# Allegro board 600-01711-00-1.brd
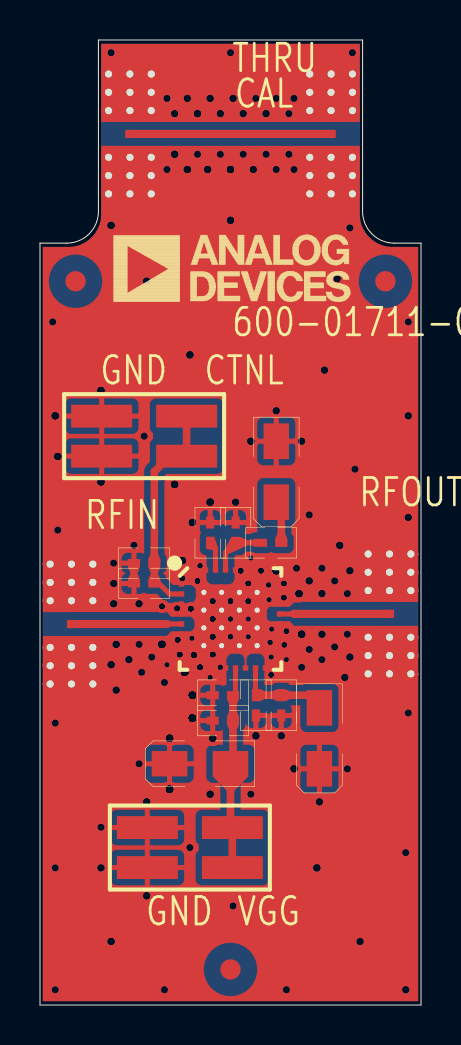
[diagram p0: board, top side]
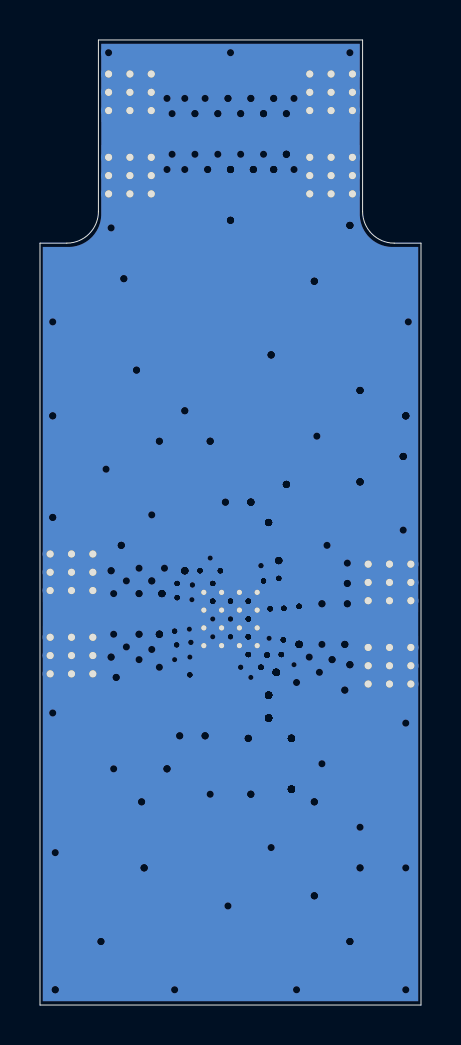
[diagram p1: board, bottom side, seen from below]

Outline 19.05 x 48.26 mm; copper layers: TOP, BOTTOM. Coordinates in mm from the lower left corner of the outline.
Outline path: 0,38.1 1.33,38.1 arc(2.46,38.56) 2.92,39.69 2.92,48.26 16.13,48.26 16.13,39.69 arc(16.59,38.56) 17.72,38.1 19.05,38.1 19.05,0 0,0 0,38.1

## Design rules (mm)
net group RF_E: nets RFIN RFOUT THRU-CAL

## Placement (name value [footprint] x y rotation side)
1  -  [FID]  9.53 1.78 0 top
2  -  [FID]  1.78 36.2 0 top
3  -  [FID]  17.27 36.2 0 top
C1  .10  [0402]  8.51 23.62 270 top
C2  .10  [0402]  5.21 21.08 180 top
C3  .10  [0402]  9.14 15.49 180 top
C4  .10  [0402]  10.79 14.99 270 top
C5  .10  [0402]  9.78 23.62 90 top
C6  .10  [0402]  5.21 22.1 180 top
C7  .10  [0402]  9.14 14.22 180 top
C8  .10  [0402]  12.06 14.99 270 top
C9  .10  [3216]  11.81 26.67 270 top
C10  .10  [3216]  13.97 13.34 270 top
C11  .10  [3216]  8 12.06 180 top
J1  -  [K_SRI-NS]  0 19.05 0 top
J2  -  [K_SRI-NS]  19.05 19.56 180 top
J3  -  [HEADER_2MM_SMT_04PIN]  5.21 28.45 90 top
J4  -  [HEADER_2MM_SMT_04PIN]  7.49 7.87 90 top
J5  -  [K_SRI-NS]  16.13 43.56 180 top
J6  -  [K_SRI-NS]  2.92 43.56 0 top
R1  .10  [0402]  11.56 23.11 0 top
U1  -  [HMC_PM5]  9.53 19.3 0 top

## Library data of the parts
1-3 = FID-UNREGISTERED
C1-C8 = CAP: alternate symbols: (01005,0201,0302BB,0402,0402-EP,0502BB,0603,0805,1206,1210,1812,1825,2220,800A,CASEL,CASES)
C9-C11 = CAP_POL: alternate symbols: (0805POL,134D-F,2214,2915,2917,3216,3528,6032,7343,CAPFM-12_5,FK-P)
J1 J2 J5 J6 = K_SRI-NS: alternate symbols: (K_SRI-44GHZ,K_SRI-NS)
J3 J4 = 87759-0414
R1 = RES: alternate symbols: (0201,0302-EP,0402,0402-EP,0505-EP,0603,0603-EP,0805,1206,1206-EP,1210,2010-EP,2512)
U1 = HMC994APM5E

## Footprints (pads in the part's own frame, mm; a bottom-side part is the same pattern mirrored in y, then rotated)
0402
  rect 0.61x0.406 smd: 1(-0.508,0) 2(0.508,0)
3216
  rect 1.778x1.27 smd: 1(1.524,0) 2(-1.524,0)
FID
  round 1.016 smd: 1(0,0)
HEADER_2MM_SMT_04PIN
  rect 1.143x3.048 smd: 1(-1,-2.125) 2(-1,2.125) 3(1,-2.125) 4(1,2.125)
HMC_PM5
  rect 0.27x0.27 smd: 1(-2.45,1.75) 2(-2.45,1.25) 3(-2.45,0.75) 4(-2.45,0.25) 5(-2.45,-0.25) 6(-2.45,-0.75) 7(-2.45,-1.25) 8(-2.45,-1.75) 9(-1.75,-2.45) 10(-1.25,-2.45) 11(-0.75,-2.45) 12(-0.25,-2.45) 13(0.25,-2.45) 14(0.75,-2.45) 15(1.25,-2.45) 16(1.75,-2.45) 17(2.45,-1.75) 18(2.45,-1.25) 19(2.45,-0.75) 20(2.45,-0.25) 21(2.45,0.25) 22(2.45,0.75) 23(2.45,1.25) 24(2.45,1.75) 25(1.75,2.45) 26(1.25,2.45) 27(0.75,2.45) 28(0.25,2.45) 29(-0.25,2.45) 30(-0.75,2.45) 31(-1.25,2.45) 32(-1.75,2.45)
  round 0.635 hole 0.254: 33(-1.333,1.333) 34(-0.445,1.333) 35(0.445,1.333) 36(1.333,1.333) 37(-1.333,0.445) 38(-0.445,0.445) 39(0.445,0.445) 40(1.333,0.445) 41(-1.333,-0.445) 42(-0.445,-0.445) 43(0.445,-0.445) 44(1.333,-0.445) 45(-1.333,-1.333) 46(-0.445,-1.333) 47(0.445,-1.333) 48(1.333,-1.333)
K_SRI-NS
  rect 0.406x0.406 smd: 1(1.549,0)
  round 0.762 hole 0.356: 2(0.508,-2.997) 3(0.508,-2.083) 4(0.508,-1.168) 5(0.508,1.168) 6(0.508,2.083) 7(0.508,2.997) 8(1.575,-2.997) 9(1.575,-2.083) 10(1.575,-1.168) 11(1.575,1.168) 12(1.575,2.083) 13(1.575,2.997) 14(2.642,-2.997) 15(2.642,-2.083) 16(2.642,-1.168) 17(2.642,1.168) 18(2.642,2.083) 19(2.642,2.997)

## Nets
GND: C1.1 C2.2 C3.2 C4.2 C5.2 C6.2 C7.2 C8.2 C9.2 C10.1 C11.1 J1.2 J1.3 J1.4 J1.5 J1.6 J1.7 J1.8 J1.9 J1.10 J1.11 J1.12 J1.13 J1.14 J1.15 J1.16 J1.17 J1.18 J1.19 J2.2 J2.3 J2.4 J2.5 J2.6 J2.7 J2.8 J2.9 J2.10 J2.11 J2.12 J2.13 J2.14 J2.15 J2.16 J2.17 J2.18 J2.19 J3.2 J3.4 J4.2 J4.4 J5.2 J5.3 J5.4 J5.5 J5.6 J5.7 J5.8 J5.9 J5.10 J5.11 J5.12 J5.13 J5.14 J5.15 J5.16 J5.17 J5.18 J5.19 J6.2 J6.3 J6.4 J6.5 J6.6 J6.7 J6.8 J6.9 J6.10 J6.11 J6.12 J6.13 J6.14 J6.15 J6.16 J6.17 J6.18 J6.19 U1.1 U1.3 U1.4 U1.6 U1.7 U1.8 U1.9 U1.10 U1.11 U1.12 U1.14 U1.16 U1.17 U1.18 U1.19 U1.20 U1.22 U1.23 U1.24 U1.25 U1.26 U1.27 U1.28 U1.31 U1.32 U1.33 U1.34 U1.35 U1.36 U1.37 U1.38 U1.39 U1.40 U1.41 U1.42 U1.43 U1.44 U1.45 U1.46 U1.47 U1.48
CNTL: C2.1 C6.1 J3.1 J3.3 U1.2
RFIN: J1.1 U1.5
RFOUT: J2.1 U1.21
THRU-CAL: J5.1 J6.1
VGG: C3.1 C7.1 C11.2 J4.1 J4.3 U1.13
$1N162: C4.1 C8.1 C10.2 U1.15
$1N213: C5.1 R1.1 U1.29
$1N283: C1.2 U1.30
$1N456: C9.1 R1.2

Pads without a net: 1 1; 2 1; 3 1

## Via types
v1: diameter 0.635, hole 0.254, TOP to BOTTOM, 420 vias
v2: diameter 0.762, hole 0.356, TOP to BOTTOM, 562 vias

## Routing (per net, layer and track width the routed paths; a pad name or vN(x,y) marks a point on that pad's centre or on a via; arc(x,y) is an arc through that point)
GND: length 26.3
  TOP w0.254: 9.78,24.75 9.78,24.43 ; 7.21,8.87 6.89,8.87 ; 1.24,29.45 1.56,29.45 ; 8.64,14.97 8.64,15.29 ; 8.64,14.74 8.64,14.43 ; 7.21,6.87 6.89,6.87 ; 4.7,22.62 4.7,22.3 ; 5.37,9.76 5.37,9.45 ; 12.76,28.19 12.45,28.19 ; 8.64,16.01 8.64,15.7 ; 8.64,13.7 8.64,14.02 ; 9.26,24.13 9.58,24.13 ; 11.81,29.4 11.81,29.08 ; 3.53,8.87 3.84,8.87 ; 12.06,13.86 12.06,14.17 ; 1.24,27.45 1.56,27.45 ; 4.08,21.08 4.39,21.08 ; 5.27,12.06 5.59,12.06 ; 5.37,7.76 5.37,7.45 ; 3.53,6.87 3.84,6.87 ; 5.37,7.98 5.37,8.3 ; 8.01,15.49 8.33,15.49 ; v1(6.1,19.94) 6.22,19.94 6.61,19.55 7.6,19.55 7.85,19.3 7.85,18.8 7.61,18.56 6.62,18.56 6.35,18.29 6.1,18.29 v2(6.1,18.03) ; 13.97,10.6 13.97,10.92 ; 4.92,27.45 4.61,27.45 ; 5.37,5.99 5.37,6.3 ; 12.59,14.48 12.27,14.48 ; v2(12.95,20.57) 12.95,20.26 12.64,20.26 12.43,20.05 11.44,20.05 11.22,19.83 11.22,19.26 11.42,19.06 12.43,19.06 12.95,18.54 v2(13.08,18.54) ; C6.2 C2.2 ; 3.08,28.56 3.08,28.88 ; 11.32,14.48 11,14.48 ; 7.68,12.06 7.37,12.06 ; 13.97,13.02 13.97,12.7 ; 10.86,28.19 11.18,28.19 ; 6.48,11.11 6.48,11.43 ; 10.79,13.86 10.79,14.17 ; 4.7,20.56 4.7,20.88 ; 3.08,26.56 3.08,26.88 ; 7.99,24.13 8.31,24.13 ; 11.81,26.99 11.81,27.3 ; 4.92,29.45 4.61,29.45 ; 3.08,28.34 3.08,28.02 ; 14.92,11.81 14.61,11.81 ; 10.3,24.13 9.98,24.13 ; 8.01,14.22 8.33,14.22 ; 9.03,24.13 8.71,24.13 ; 6.48,13.02 6.48,12.7 ; 11.54,14.48 11.86,14.48 ; 13.02,11.81 13.34,11.81 ; 3.08,30.34 3.08,30.02 ; 8.51,24.75 8.51,24.43 ; 4.08,22.1 4.39,22.1
  vias: v1(6.35,17.02) v1(6.86,19.84) v1(6.86,19.84) v1(6.86,19.84) v1(6.86,19.84) v1(6.86,19.84) v1(6.86,19.84) v1(6.86,19.84) v1(6.86,19.84) v1(6.86,19.84) v1(6.86,19.84) v1(6.86,19.84) v1(6.86,19.84) v1(6.86,19.84) v1(6.86,19.84) v1(6.86,19.84) v1(6.86,19.84) v1(6.88,18.26) v1(6.88,18.26) v1(6.88,18.26) v1(6.88,18.26) v1(6.88,18.26) v1(6.88,18.26) v1(6.88,18.26) v1(6.88,18.26) v1(6.88,18.26) v1(6.88,18.26) v1(6.88,18.26) v1(6.88,18.26) v1(6.88,18.26) v1(6.88,18.26) v1(6.88,18.26) v1(6.88,18.26) v1(6.88,18.26) v1(6.88,18.26) v1(6.88,18.26) v1(6.88,18.26) v1(6.88,18.26) v1(6.88,18.26) v1(6.99,17.53) v1(6.99,17.53) v1(6.99,17.53) v1(6.99,17.53) v1(6.99,17.53) v1(6.99,17.53) v1(6.99,17.53) v1(6.99,17.53) v1(6.99,17.53) v1(6.99,17.53) v1(6.99,17.53) v1(6.99,17.53) v1(6.99,17.53) v1(6.99,17.53) v1(6.99,17.53) v1(6.99,17.53) v1(6.99,17.53) v1(6.99,17.53) v1(6.99,17.53) v1(6.99,17.53) v1(6.99,17.53) v1(6.99,17.53) v1(7.11,21.34) v1(7.11,21.34) v1(7.11,21.34) v1(7.11,21.34) v1(7.11,21.34) v1(7.11,21.34) v1(7.11,21.34) v1(7.11,21.34) v1(7.11,21.34) v1(7.11,21.34) v1(7.54,19.81) v1(7.54,19.81) v1(7.54,19.81) v1(7.54,19.81) v1(7.54,19.81) v1(7.54,19.81) v1(7.54,19.81) v1(7.54,19.81) v1(7.54,19.81) v1(7.54,19.81) v1(7.54,19.81) v1(7.54,19.81) v1(7.54,19.81) v1(7.54,19.81) v1(7.59,18.34) v1(7.7,17.5) v1(7.7,17.5) v1(7.7,17.5) v1(7.7,17.5) v1(7.7,17.5) v1(7.7,17.5) v1(7.7,17.5) v1(7.7,17.5) v1(7.7,17.5) v1(7.7,17.5) v1(7.7,17.5) v1(7.7,17.5) v1(7.7,17.5) v1(7.7,17.5) v1(7.7,17.5) v1(7.7,17.5) v1(7.7,17.5) v1(7.7,17.5) v1(7.7,17.5) v1(7.7,17.5) v1(7.7,17.5) v1(7.7,17.5) v1(7.7,17.5) v1(7.7,17.5) v1(7.7,17.5) v1(7.7,17.5) v1(7.7,17.5) v1(7.7,17.5) v1(7.7,17.5) v1(7.7,17.5) v1(7.7,17.5) v1(7.7,17.5) v1(7.7,17.5) v1(7.7,17.5) v1(7.7,17.5) v1(7.7,17.5) v1(7.7,17.5) v1(7.7,17.5) v1(7.7,17.5) v1(7.7,17.5) v1(7.7,17.5) v1(7.7,17.5) v1(7.7,17.5) v1(7.7,17.5) v1(7.7,17.5) v1(7.7,17.5) v1(7.7,17.5) v1(7.87,21.21) v1(7.87,21.21) v1(7.87,21.21) v1(7.87,21.21) v1(7.87,21.21) v1(7.87,21.21) v1(7.87,21.21) v1(7.87,21.21) v1(7.87,21.21) v1(7.87,21.21) v1(7.87,21.21) v1(7.87,21.21) v1(7.87,21.21) v1(8,21.97) v1(8,21.97) v1(8,16.89) v1(8,16.89) v1(8,16.89) v1(8,16.89) v1(8,16.89) v1(8,16.89) v1(8,16.89) v1(8,16.89) v1(8,16.89) v1(8,16.89) v1(8,16.89) v1(8,16.89) v1(8,16.89) v1(8,16.89) v1(8,16.89) v1(8,16.89) v1(8,16.89) v1(8,16.89) v1(8,16.89) v1(8,16.89) v1(8,16.89) v1(8,16.89) v1(8,16.89) v1(8,16.89) v1(8,16.89) v1(8,16.89) v1(8,16.89) v1(8,16.89) v1(8,16.89) v1(8,16.89) v1(8,16.89) v1(8,16.89) v1(8,16.89) v1(8,16.89) v1(8,16.89) v1(8,16.89) v1(8,16.89) v1(8,16.89) v1(8,16.89) v1(8,16.89) v1(8,16.89) v1(8,16.89) v1(8,16.89) v1(8,16.89) v1(8,16.89) v1(8,16.89) v1(8,16.89) v1(8,16.89) v1(8,16.89) v1(8,16.89) v1(8,16.89) v1(8,16.89) v1(8.51,16.38) v1(8.64,20.19) v1(8.64,20.19) v1(8.64,20.19) v1(8.64,20.19) v1(8.64,20.19) v1(8.64,20.19) v1(8.64,20.19) v1(8.64,20.19) v1(8.64,20.19) v1(8.64,20.19) v1(8.64,20.19) v1(8.64,20.19) v1(8.64,20.19) v1(8.64,20.19) v1(8.64,20.19) v1(8.64,20.19) v1(8.64,19.3) v1(8.64,19.3) v1(8.64,19.3) v1(8.64,19.3) v1(8.64,19.3) v1(8.64,19.3) v1(8.64,19.3) v1(8.64,19.3) v1(8.64,19.3) v1(8.64,19.3) v1(8.64,19.3) v1(8.64,19.3) v1(8.64,19.3) v1(8.64,19.3) v1(8.64,19.3) v1(8.64,19.3) v1(8.64,19.3) v1(8.64,19.3) v1(8.64,19.3) v1(8.64,18.41) v1(8.64,18.41) v1(8.64,18.41) v1(8.64,18.41) v1(8.64,18.41) v1(8.64,18.41) v1(8.64,18.41) v1(8.64,18.41) v1(8.64,18.41) v1(8.64,18.41) v1(8.64,18.41) v1(8.64,18.41) v1(8.64,18.41) v1(8.64,18.41) v1(8.64,18.41) v1(8.64,18.41) v1(8.64,18.41) v1(8.64,18.41) v1(8.64,18.41) v1(8.64,18.41) v1(8.64,18.41) v1(8.64,18.41) v1(8.64,18.41) v1(8.64,17.53) v1(8.64,17.53) v1(8.64,17.53) v1(8.64,17.53) v1(8.64,17.53) v1(8.64,17.53) v1(8.64,17.53) v1(8.64,17.53) v1(8.64,17.53) v1(8.64,17.53) v1(8.64,17.53) v1(8.64,17.53) v1(8.64,17.53) v1(8.64,17.53) v1(8.64,17.53) v1(8.64,17.53) v1(8.64,17.53) v1(8.64,17.53) v1(8.64,17.53) v1(8.64,17.53) v1(8.64,17.53) v1(8.64,17.53) v1(8.64,17.53) v1(8.64,17.53) v1(8.64,17.53) v1(9.02,16.89) v1(9.02,16.89) v1(9.53,20.19) v1(9.53,20.19) v1(9.53,20.19) v1(9.53,20.19) v1(9.53,20.19) v1(9.53,20.19) v1(9.53,20.19) v1(9.53,20.19) v1(9.53,20.19) v1(9.53,20.19) v1(9.53,20.19) v1(9.53,20.19) v1(9.53,20.19) v1(9.53,20.19) v1(9.53,20.19) v1(9.53,19.3) v1(9.53,19.3) v1(9.53,18.41) v1(9.53,18.41) v1(9.53,18.41) v1(10.03,21.72) v1(10.03,21.72) v1(10.03,21.72) v1(10.03,21.72) v1(10.03,21.72) v1(10.03,21.72) v1(10.03,21.72) v1(10.03,21.72) v1(10.03,21.72) v1(10.03,21.72) v1(10.03,21.72) v1(10.03,21.72) v1(10.03,21.72) v1(10.03,21.72) v1(10.41,21.08) v1(10.41,21.08) v1(10.41,21.08) v1(10.41,21.08) v1(10.41,21.08) v1(10.41,21.08) v1(10.41,21.08) v1(10.41,21.08) v1(10.41,21.08) v1(10.41,21.08) v1(10.41,21.08) v1(10.41,21.08) v1(10.41,21.08) v1(10.41,20.19) v1(10.41,20.19) v1(10.41,20.19) v1(10.41,20.19) v1(10.41,20.19) v1(10.41,20.19) v1(10.41,20.19) v1(10.41,20.19) v1(10.41,20.19) v1(10.41,20.19) v1(10.41,20.19) v1(10.41,20.19) v1(10.41,20.19) v1(10.41,20.19) v1(10.41,19.3) v1(10.41,18.41) v1(10.54,22.35) v1(11.05,21.72) v1(11.05,21.72) v1(11.05,21.72) v1(11.05,21.72) v1(11.05,21.72) v1(11.05,21.72) v1(11.05,21.72) v1(11.05,21.72) v1(11.05,21.72) v1(11.05,21.72) v1(11.05,21.72) v1(11.43,21.01) v1(11.43,21.01) v1(11.46,20.27) v1(11.51,18.14) v1(11.51,18.14) v1(11.58,18.8) v1(11.56,17.4) v1(11.56,16.51) v1(11.56,16.51) v1(11.56,16.51) v1(11.56,16.51) v1(11.56,16.51) v1(11.56,16.51) v1(12.19,21.08) v1(12.19,21.08) v1(12.19,21.08) v1(12.19,21.08) v1(12.19,21.08) v1(12.19,21.08) v1(12.19,21.08) v1(12.19,21.08) v1(12.19,21.08) v1(12.19,21.08) v1(12.19,20.37) v1(12.19,20.37) v1(12.19,20.37) v1(12.19,20.37) v1(12.19,20.37) v1(12.19,20.37) v1(12.19,20.37) v1(12.19,20.37) v1(12.22,18.01) v1(12.22,18.01) v1(12.22,18.01) v1(12.22,18.01) v1(12.32,18.69) v1(12.32,18.69) v1(12.32,18.69) v1(12.32,18.69) v1(12.32,18.69) v1(12.32,17.27) v2(0.64,34.16) v2(0.76,29.46) v2(0.76,29.46) v2(0.76,29.46) v2(0.76,29.46) v2(0.76,29.46) v2(0.76,29.46) v2(0.76,14.1) v2(0.76,6.86) v2(0.76,0.76) v2(0.89,27.43) v2(0.89,27.43) v2(0.89,27.43) v2(0.89,27.43) v2(0.89,27.43) v2(0.89,27.43) v2(0.89,23.75) v2(3.05,30.73) v2(3.05,30.73) v2(3.05,30.73) v2(3.05,30.73) v2(3.05,30.73) v2(3.05,26.16) v2(3.05,26.16) v2(3.05,26.16) v2(3.05,26.16) v2(3.05,26.16) v2(3.05,26.16) v2(3.05,8.89) v2(3.05,6.86) v2(3.05,6.86) v2(3.56,47.62) v2(3.56,38.99) v2(3.56,38.99) v2(3.56,38.99) v2(3.56,38.99) v2(3.56,17.02) v2(3.56,17.02) v2(3.56,17.02) v2(3.56,3.17) v2(3.56,3.17) v2(3.56,3.17) v2(3.68,22.1) v2(3.68,21.08) v2(3.68,21.08) v2(3.68,20.07) v2(3.68,20.07) v2(3.81,18.03) v2(3.81,18.03) v2(3.81,18.03) v2(3.81,15.75) v2(3.81,15.75) v2(4.45,17.27) v2(4.45,17.27) v2(4.7,22.99) v2(4.95,20.07) v2(4.95,20.07) v2(4.95,18.03) v2(4.95,12.06) v2(5.08,16.64) v2(5.21,28.45) v2(5.33,36.2) v2(5.33,36.2) v2(5.33,36.2) v2(5.33,36.2) v2(5.33,10.16) v2(5.33,10.16) v2(5.33,10.16) v2(5.33,5.46) v2(5.33,5.46) v2(5.33,5.46) v2(5.59,17.4) v2(6.22,16.13) v2(6.22,0.76) v2(6.35,45.34) v2(6.35,41.78) v2(6.48,13.34) v2(6.48,13.34) v2(6.48,13.34) v2(6.48,13.34) v2(6.48,13.34) v2(6.48,13.34) v2(6.48,13.34) v2(6.48,13.34) v2(6.48,13.34) v2(6.48,13.34) v2(6.48,13.34) v2(6.48,13.34) v2(6.48,13.34) v2(6.48,13.34) v2(6.48,13.34) v2(6.48,13.34) v2(6.48,13.34) v2(6.48,13.34) v2(6.48,13.34) v2(6.48,13.34) v2(6.48,13.34) v2(6.48,13.34) v2(6.48,13.34) v2(6.48,13.34) v2(6.48,13.34) v2(6.48,13.34) v2(6.48,13.34) v2(6.48,13.34) v2(6.48,13.34) v2(6.48,13.34) v2(6.48,13.34) v2(6.48,13.34) v2(6.48,13.34) v2(6.48,13.34) v2(6.48,13.34) v2(6.48,13.34) v2(6.48,13.34) v2(6.48,13.34) v2(6.48,13.34) v2(6.48,13.34) v2(6.48,13.34) v2(6.48,13.34) v2(6.48,13.34) v2(6.48,13.34) v2(6.48,13.34) v2(6.48,13.34) v2(6.48,13.34) v2(6.48,13.34) v2(6.48,13.34) v2(6.48,13.34) v2(6.48,13.34) v2(6.48,13.34) v2(6.48,13.34) v2(6.48,13.34) v2(6.48,13.34) v2(6.48,13.34) v2(6.48,10.79) v2(6.48,10.79) v2(6.48,10.79) v2(6.48,10.79) v2(6.48,10.79) v2(6.48,10.79) v2(6.48,10.79) v2(6.48,10.79) v2(6.48,10.79) v2(6.48,10.79) v2(6.48,10.79) v2(6.48,10.79) v2(6.48,10.79) v2(6.48,10.79) v2(6.48,10.79) v2(6.48,10.79) v2(6.48,10.79) v2(6.48,10.79) v2(6.48,10.79) v2(6.48,10.79) v2(6.48,10.79) v2(6.48,10.79) v2(6.48,10.79) v2(6.48,10.79) v2(6.48,10.79) v2(6.48,10.79) v2(6.48,10.79) v2(6.48,10.79) v2(6.48,10.79) v2(6.48,10.79) v2(6.48,10.79) v2(6.48,10.79) v2(6.48,10.79) v2(6.48,10.79) v2(6.48,10.79) v2(6.48,10.79) v2(6.48,10.79) v2(6.48,10.79) v2(6.48,10.79) v2(6.48,10.79) v2(6.48,10.79) v2(6.48,10.79) v2(6.48,10.79) v2(6.48,10.79) v2(6.48,10.79) v2(6.48,10.79) v2(6.48,10.79) v2(6.48,10.79) v2(6.48,10.79) v2(6.48,10.79) v2(6.48,10.79) v2(6.48,10.79) v2(6.48,10.79) v2(6.48,10.79) v2(6.48,10.79) v2(6.48,10.79) v2(6.48,10.79) v2(6.48,10.79) v2(6.48,10.79) v2(6.73,44.58) v2(6.73,44.58) v2(6.73,42.55) v2(6.73,42.55) v2(6.73,42.55) v2(6.73,42.55) v2(6.73,26.04) v2(6.73,26.04) v2(6.73,26.04) v2(6.73,26.04) v2(6.73,26.04) v2(6.73,26.04) v2(6.73,26.04) v2(7.11,22.23) v2(7.11,22.23) v2(7.11,22.23) v2(7.11,22.23) v2(7.11,22.23) v2(7.11,22.23) v2(7.11,22.23) v2(7.11,22.23) v2(7.11,22.23) v2(7.24,16.64) v2(7.24,16.64) v2(7.24,16.64) v2(7.24,16.64) v2(7.24,16.64) v2(7.24,16.64) v2(7.24,16.64) v2(7.24,16.64) v2(7.24,16.64) v2(7.24,16.64) v2(7.24,16.64) v2(7.24,16.64) v2(7.24,16.64) v2(7.24,16.64) v2(7.24,16.64) v2(7.24,16.64) v2(7.24,16.64) v2(7.24,16.64) v2(7.24,16.64) v2(7.24,16.64) v2(7.24,16.64) v2(7.24,16.64) v2(7.24,16.64) v2(7.24,16.64) v2(7.24,16.64) v2(7.24,16.64) v2(7.24,16.64) v2(7.24,16.64) v2(7.24,16.64) v2(7.24,16.64) v2(7.24,16.64) v2(7.24,16.64) v2(7.24,16.64) v2(7.24,16.64) v2(7.24,16.64) v2(7.24,16.64) v2(7.24,16.64) v2(7.24,16.64) v2(7.24,16.64) v2(7.24,16.64) v2(7.24,16.64) v2(7.24,16.64) v2(7.24,16.64) v2(7.24,16.64) v2(7.24,16.64) v2(7.24,16.64) v2(7.24,16.64) v2(7.24,16.64) v2(7.24,16.64) v2(7.24,16.64) v2(7.24,16.64) v2(7.24,16.64) v2(7.37,45.34) v2(7.37,45.34) v2(7.37,41.78) v2(7.37,41.78) v2(7.37,41.78) v2(7.37,41.78) v2(7.49,32.51) v2(7.49,32.51) v2(7.49,32.51) v2(7.49,32.51) v2(7.49,7.87) v2(7.62,24.13) v2(7.62,24.13) v2(7.62,24.13) v2(7.62,24.13) v2(7.62,24.13) v2(7.62,24.13) v2(7.62,24.13) v2(7.62,24.13) v2(7.62,24.13) v2(7.62,15.49) v2(7.62,15.49) v2(7.62,15.49) v2(7.62,15.49) v2(7.62,15.49) v2(7.62,15.49) v2(7.62,15.49) v2(7.62,15.49) v2(7.62,15.49) v2(7.62,15.49) v2(7.62,15.49) v2(7.62,15.49) v2(7.62,15.49) v2(7.62,15.49) v2(7.62,15.49) v2(7.62,15.49) v2(7.62,15.49) v2(7.62,15.49) v2(7.62,15.49) v2(7.62,15.49) v2(7.62,15.49) v2(7.62,15.49) v2(7.62,15.49) v2(7.62,15.49) v2(7.62,15.49) v2(7.62,15.49) v2(7.62,15.49) v2(7.62,15.49) v2(7.62,15.49) v2(7.62,15.49) v2(7.62,15.49) v2(7.62,15.49) v2(7.62,15.49) v2(7.62,15.49) v2(7.62,15.49) v2(7.62,15.49) v2(7.62,15.49) v2(7.62,15.49) v2(7.62,15.49) v2(7.62,15.49) v2(7.62,15.49) v2(7.62,15.49) v2(7.62,15.49) v2(7.62,15.49) v2(7.62,15.49) v2(7.62,15.49) v2(7.62,15.49) v2(7.62,15.49) v2(7.62,15.49) v2(7.62,15.49) v2(7.62,15.49) v2(7.62,15.49) v2(7.62,14.35) v2(7.62,14.35) v2(7.62,14.35) v2(7.62,14.35) v2(7.62,14.35) v2(7.62,14.35) v2(7.62,14.35) v2(7.62,14.35) v2(7.62,14.35) v2(7.62,14.35) v2(7.62,14.35) v2(7.62,14.35) v2(7.62,14.35) v2(7.62,14.35) v2(7.62,14.35) v2(7.62,14.35) v2(7.62,14.35) v2(7.62,14.35) v2(7.62,14.35) v2(7.62,14.35) v2(7.62,14.35) v2(7.62,14.35) v2(7.62,14.35) v2(7.62,14.35) v2(7.62,14.35) v2(7.62,14.35) v2(7.62,14.35) v2(7.62,14.35) v2(7.62,14.35) v2(7.62,14.35) v2(7.62,14.35) v2(7.62,14.35) v2(7.62,14.35) v2(7.62,14.35) v2(7.62,14.35) v2(7.62,14.35) v2(7.62,14.35) v2(7.62,14.35) v2(7.62,14.35) v2(7.62,14.35) v2(7.62,14.35) v2(7.62,14.35) v2(7.62,14.35) v2(7.62,14.35) v2(7.62,14.35) v2(7.62,14.35) v2(7.62,14.35) v2(7.62,14.35) v2(7.62,14.35) v2(7.62,14.35) v2(7.62,14.35) v2(7.62,14.35) v2(7.62,14.35) v2(7.62,14.35) v2(7.62,14.35) v2(7.62,14.35) v2(7.87,44.58) v2(7.87,44.58) v2(7.87,44.58) v2(7.87,42.55) v2(8.38,41.78) v2(8.38,41.78) v2(8.38,41.78) v2(8.38,41.78) v2(8.51,45.34) v2(8.51,45.34) v2(8.51,25.15) v2(8.51,25.15) v2(8.51,25.15) v2(8.51,25.15) v2(8.51,25.15) v2(8.51,25.15) v2(8.51,25.15) v2(8.51,25.15) v2(8.51,10.54) v2(8.51,10.54) v2(8.51,10.54) v2(8.64,13.34) v2(8.64,13.34) v2(8.64,13.34) v2(8.64,13.34) v2(9.02,44.58) v2(9.02,44.58) v2(9.02,42.55) v2(9.53,47.62) v2(9.53,41.78) v2(9.53,41.78) v2(9.53,41.78) v2(9.53,41.78) v2(9.53,41.78) v2(9.53,39.24) v2(9.53,39.24) v2(9.53,39.24) v2(9.53,39.24) v2(9.65,45.34) v2(9.65,45.34) v2(9.65,4.95) v2(9.78,25.15) v2(9.78,25.15) v2(10.16,44.58) v2(10.16,44.58) v2(10.16,42.55) v2(10.54,28.19) v2(10.54,28.19) v2(10.54,28.19) v2(10.54,10.54) v2(10.67,41.78) v2(10.67,41.78) v2(10.79,45.34) v2(10.79,13.46) v2(10.79,13.46) v2(10.79,13.46) v2(11.3,44.58) v2(11.3,44.58) v2(11.3,42.55) v2(11.81,45.34) v2(11.81,41.78) v2(11.81,29.72) v2(11.81,29.72) v2(11.81,21.72) v2(11.81,21.72) v2(11.81,21.72) v2(11.81,21.72) v2(11.81,21.72) v2(11.81,21.72) v2(11.81,21.72) v2(11.81,21.72) v2(11.81,21.72) v2(11.81,21.72) v2(12.06,13.46) v2(12.06,13.46) v2(12.32,0.76) v2(12.45,44.58) v2(12.45,42.55) v2(12.7,45.34) v2(12.7,41.78) v2(12.7,11.81) v2(12.7,11.81) v2(12.7,11.81) v2(12.83,21.84) v2(13.08,28.19) v2(13.08,28.19) v2(13.08,16.89) v2(13.46,24.51) v2(13.46,21.21) v2(13.46,21.21) v2(13.46,17.78) v2(13.84,6.86) v2(13.84,6.86) v2(13.84,6.86) v2(13.97,10.16) v2(13.97,10.16) v2(14.1,21.84) v2(14.1,20.57) v2(14.1,20.57) v2(14.1,18.54) v2(14.1,18.54) v2(14.1,17.27) v2(14.22,31.75) v2(14.22,31.75) v2(14.73,21.21) v2(14.73,17.91) v2(14.86,36.32) v2(14.86,36.32) v2(14.99,22.99) v2(14.99,22.99) v2(14.99,22.99) v2(15.24,16.38) v2(15.24,16.38) v2(15.37,20.57) v2(15.37,18.54) v2(15.37,11.81) v2(15.49,38.86) v2(15.49,21.72) v2(15.49,21.72) v2(15.49,17.4) v2(15.49,17.4) v2(15.62,47.62) v2(15.75,26.8) v2(16,3.17) v2(16,3.17) v2(18.29,7.62) v2(18.29,0.76) v2(18.29,0.76) v2(18.41,34.16) v2(18.41,29.46) v2(18.41,29.46) v2(18.41,24.38) v2(18.41,24.38) v2(18.41,14.61)
CNTL: length 11.3
  TOP w0.254: U1.2 6.48,20.55 5.97,21.06 5.71,21.06 C2.1 C6.1
  TOP w0.381: C6.1 5.71,26.67 6.1,27.05 6.1,27.45 J3.1 J3.3
RFIN: length 5.5
  TOP w0.254: U1.5 6.35,19.05
  TOP w0.406: J1.1 1.55,19.05 6.35,19.05
RFOUT: length 5.5
  TOP w0.254: U1.21 12.69,19.55 12.7,19.56
  TOP w0.406: J2.1 17.5,19.56 12.7,19.56 12.7,19.56
THRU-CAL: length 10.1
  TOP w0.406: J5.1 J6.1
VGG: length 10.2
  TOP w0.254: C3.1 9.77,15.5 U1.13
  TOP w0.381: C3.1 C7.1 9.65,12.19 C11.2 9.53,8.97 J4.3 J4.1
$1N162: length 5.2
  TOP w0.254: C4.1 10.77,15.51 U1.15
  TOP w0.381: C4.1 C8.1 13.97,15.49 C10.2
$1N213: length 2.8
  TOP w0.254: R1.1 C5.1 9.28,22.61 U1.29
$1N283: length 1.5
  TOP w0.254: U1.30 8.77,22.85 C1.2
$1N456: length 2.1
  TOP w0.381: 12.06,23.11 12.06,24.89 C9.1

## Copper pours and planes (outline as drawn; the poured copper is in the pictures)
GND on TOP (solid shape): 15.99,44.16 3.06,44.16 3.06,48.07 15.99,48.07
GND on TOP (solid shape): outline of 1534 points within 0.14,0.19 18.91,42.96
GND on BOTTOM (solid shape): 15.99,39.55 16.47,38.39 17.63,37.91 18.91,37.91 18.91,0.19 0.14,0.19 0.14,37.91 1.42,37.91 2.58,38.39 3.06,39.55 3.06,48.07 15.99,48.07
VGG on TOP (solid shape): 10.41,11.43 9.64,10.64 9.53,10.6 9.41,10.64 8.64,11.43 9.53,12.11

Small or netless copper shapes (teardrops, artwork), in the pictures only: 16 on TOP

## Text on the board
BOTTOM: METAL-02
Board Geometry/Soldermask Bottom: SOLDERMASK-02
TOP: METAL-01
Board Geometry/Soldermask Top: SOLDERMASK-01
Ref Des/Silkscreen Top: RFIN | GND | CTNL | THRU | 600-01711-00-1 | CAL | VGG | RFOUT | SILKSCREEN-01
DIMENSION: 1.900 | .400 | .030 | .635 | .750 | .115 | 2X R.062
ALL: ANALOG DEVICES | 600-01711-00-1
